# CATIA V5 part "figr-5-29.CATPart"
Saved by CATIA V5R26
Part number: Part1
Bounding box of the stored display mesh (mm): x -100 to 100, y -100 to 100, z 0 to 57
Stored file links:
  D:\_Deepak\CATIA\CATIA V5-6R2016_Deepak\Resources\Part files\Partfiles\c05_catia_v5_6r2016_prt\figr-5-29.CATPart
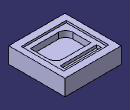
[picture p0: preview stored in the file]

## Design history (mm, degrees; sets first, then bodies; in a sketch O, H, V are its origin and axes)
Body1 (main body)
  Sketch1 on xy-plane, origin (0, 0, 0), H (1, 0, 0), V (0, 1, 0)
    line L1 (-100, 100) -> (100, 100)
    line L2 (100, 100) -> (100, -100)
    line L3 (100, -100) -> (-100, -100)
    line L4 (-100, -100) -> (-100, 100)
    axis line L5 (100, -100) -> (-100, 100)
    length L3 = 200
    length L2 = 200
    horizontal: L1 H, L3 H
    vertical: L2 V, L4 V
    midpoint: L5 O
  Pad1: profile Sketch1, direction (0, 0, 1), length 57
  Sketch2 on face of Pad1, origin (0, 0, 57), H (1, 0, 0), V (0, 1, 0)
    line L1 (-80.0557, 75.5465) -> (80.0557, 75.5465)
    line L2 (80.0557, 75.5465) -> (80.0557, -75.5465)
    line L3 (80.0557, -75.5465) -> (-80.0557, -75.5465)
    line L4 (-80.0557, -75.5465) -> (-80.0557, 75.5465)
    axis line L5 (80.0557, -75.5465) -> (-80.0557, 75.5465)
    line L6 (-62.1297, 30.1268) -> (-62.1297, -34.9955)
    arc A1 centre (-37.2362, -34.9955) radius 24.8935 from (-62.1297, -34.9955) to (-37.2362, -59.889) ccw
    line L7 (-37.2362, -59.889) -> (63.4636, -59.889)
    point P9 (63.4636, -59.889)
    line L8 (63.4636, -59.889) -> (63.4636, 3.0218)
    arc A2 centre (36.331, 3.0218) radius 27.1326 from (63.4636, 3.0218) to (35.1072, 30.1268) ccw
    line L9 (35.1072, 30.1268) -> (-62.1297, 30.1268)
    point P13 (-66.3387, 62.6022)
    line L10 (-66.3387, 62.6022) -> (63.4636, 62.6022)
    line L11 (63.4636, 62.6022) -> (63.4636, 45.9932)
    line L12 (63.4636, 45.9932) -> (-66.3387, 45.9932)
    line L13 (-66.3387, 45.9932) -> (-66.3387, 62.6022)
    point P15 (63.4636, 45.9932)
    horizontal: L1 H, L3 H, L9 H, L10 H, L12 H
    vertical: L2 V, L4 V, L6 V, L8 V, L11 V, L13 V
    midpoint: O L5
    tangency: A1 L6, L7 A1, A2 L5, A2 L8
    coincidence: P9 L5, P13 L5, P15 L8
  MultiPocket1: profile Sketch2, domains (length 17; length 28; length 7)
